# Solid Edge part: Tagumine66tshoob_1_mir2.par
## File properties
Author: KULL
Template: Iso Metric Part.par
Last saved by: KULL
Revision: 2
Application: Solid Edge
Density: 2712,000 kg/m^3
Accuracy: 0,990
Username: KULL
Material: Aluminum, 1060
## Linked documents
Tagumine66tshoob_1.par
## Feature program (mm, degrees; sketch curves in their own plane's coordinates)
part copy "CopiedPart_1"
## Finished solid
Body 1: solid body, 578 faces, 1234 edges, 670 vertices.
  Faces by surface: blend 365, spline 59, sphere 55, plane 30, cylinder 28, torus 27, offset 13, cone 1
  Edges by curve: intersection 729, circle 467, line 37, curve on surface 1
Bounding box of the edges (mm; curved faces can reach further): 84.000 x 73.183 x 18.177, from (-384.46, -113.1829, -2.3663) to (-300.46, -40, 15.811).
Cylindrical faces by radius (mm): R0.4 x6, R1.5 x1, R2.5 x2, R2.9732 x1, R5 x4, R7 x2, R7.9504 x1, R8.5905 x1, R9.9504 x1, R10.5905 x1, R10.611 x1, R12.611 x1, R20 x2, R21.7545 x1, R22 x2, R23.7545 x1
Conical faces (half-angle, radius in mm at the cone's reference point): 40.1033 deg R3.865 x1
Toroidal faces (ring radius, tube radius in mm): R2.5732 r0.4 x2, R3.9041 r0.4 x1, R4.4 r0.6 x8, R4.5371 r1.485 x1, R4.996 r0.6 x1, R5.3 r0.3 x8, R5.7982 r0.6 x1, R6 r1 x4, R6.9857 r1 x1
Spherical faces by radius (mm): R0.1 x53, R4 x1, R6 x1
Planar faces by outward normal: +x 9, -x 9, oblique 12
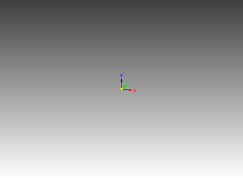
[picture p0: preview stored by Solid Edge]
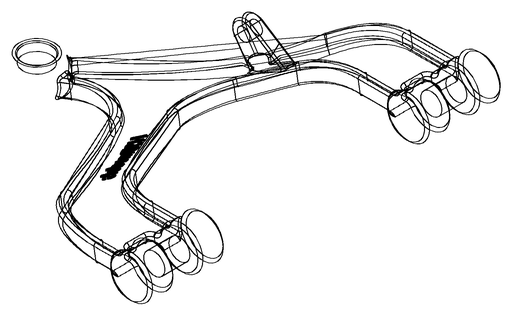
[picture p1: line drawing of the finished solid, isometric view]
